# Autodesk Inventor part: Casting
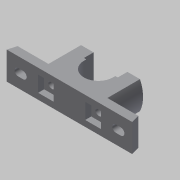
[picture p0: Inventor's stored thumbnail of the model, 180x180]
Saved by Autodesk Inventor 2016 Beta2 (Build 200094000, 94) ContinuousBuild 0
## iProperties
Created: 2009-04
Part Number: Casting
Document SubType Name: Modeling
Designer: Sham
Density: 1 g/cm^3
Material: Generic
Appearance: Default
Author: Sham
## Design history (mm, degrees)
sketch "Sketch1"
  geometry: L1 (-104, 0)-(104, 0); L2 (-104, 0)-(-100, 14); L3 (-100, 14)-(100, 14); L4 (100, 14)-(104, 0); 1 further point
  constraints: 8 end point, 1 horizontal, 1 midpoint, 1 parallel, 1 other
  dimensions: "d0" = 208 distance of L1.start L1.end; "d1" = 104 distance of L1.end point (0, 0); "d2" = 4 horizontal distance of L1.start L2.end; "d3" = 4 horizontal distance of L1.end L3.end; "d10" = 14 distance between parallel lines of L1 L3
extrude "Extrusion1" new body sketch "Sketch1" stored distance "d4" = 46; taper "d5" = 0 deg
sketch "Sketch2"
  geometry: L1 (51.143, 46)-(148.857, 46); L2 (148.857, 0)-(51.143, 0); A1 r 54 centre (100, 23) between (51.143, 46) and (51.143, 0); A2 r 54 centre (100, 23) between (148.857, 0) and (148.857, 46)
  constraints: 4 end point, 4 point on circle, 2 centre point, 1 parallel
extrude "Extrusion2" join sketch "Sketch2" distance "d8" = 54; taper "d9" = 0 deg
sketch "Sketch3"
  geometry: L1 (-28, 68)-(-28, 52); L2 (-28, 52)-(-24, 52); L3 (28, 68)-(28, 52); L4 (28, 52)-(24, 52); L5 (-28, 68)-(28, 68); L6 (-100, 14)-(-48.857, 14) reference; L7 (0, 48)-(0, 19); L8 (48.857, 14)-(100, 14) reference; L9 (48.857, 68)-(-48.857, 68) reference; L10 (-24, 48)-(-24, 52); L11 (24, 48)-(24, 52); A1 r 24 centre (0, 48) between (-24, 48) and (24, 48); 1 further point
  constraints: 16 end point, 5 perpendicular, 2 point on circle, 2 symmetric about line, 1 centre point, 1 tangent, 1 vertical alignment, 1 other
  dimensions: "d11" = 16 distance of L1.start L1.end; "d16" = 24 radius of A1; "d17" = 16 distance of L3.start L3.end; "d52" = 56 distance between parallel lines of L1 L3; "d54" = 54 distance between parallel lines of L8 L9 (derived)
extrude "Extrusion3" cut sketch "Sketch3" distance "d18" = 54; taper "d19" = 0 deg
sketch "Sketch4"
  geometry: L1 (-23, 29)-(-15, 29); L2 (-15, 17)-(-23, 17); L3 (-185, 29)-(-177, 29); L4 (-177, 17)-(-185, 17); A1 r 6 centre (-15, 23) between (-15, 17) and (-15, 29); A2 r 6 centre (-23, 23) between (-23, 29) and (-23, 17); A3 r 6 centre (-177, 23) between (-177, 17) and (-177, 29); A4 r 6 centre (-185, 23) between (-185, 29) and (-185, 17)
  constraints: 8 end point, 8 point on circle, 8 tangent, 4 centre point, 3 parallel
  dimensions: "d20" = 8 distance of A1.centre A2.centre; "d21" = 6 radius of A1; "d24" = 6 radius of A3; "d25" = 8 distance of A4.centre A3.centre
extrude "Extrusion4" cut sketch "Sketch4" distance "d28" = 54; taper "d29" = 0 deg
sketch "Sketch5"
  geometry: L1 (208, 0)-(0, 0) reference; L2 (52, -10)-(78, -10); L3 (78, -10)-(78, -36); L4 (78, -36)-(52, -36); L5 (52, -36)-(52, -10); L6 (130, -10)-(156, -10); L7 (156, -10)-(156, -36); L8 (156, -36)-(130, -36); L9 (130, -36)-(130, -10); L10 (0, -46)-(208, -46) reference; L11 (104, -23)-(104, -46)
  constraints: 18 end point, 5 perpendicular, 4 parallel, 2 horizontal, 1 midpoint
  dimensions: "d30" = 26 distance of L2.start L2.end; "d31" = 10 distance between parallel lines of L2 L1; "d32" = 10 distance between parallel lines of L1 L6; "d65" = 26 distance between parallel lines of L3 L11; "d66" = 26 distance between parallel lines of L9 L11
extrude "Extrusion5" cut sketch "Sketch5" distance "d34" = 10; taper "d35" = 0 deg
sketch "Sketch6"
  geometry: L1 (148.857, 0)-(128, 0) reference; L2 (72, 0)-(51.143, 0) reference; L3 (0, 46)-(0, 0) reference; L4 (200, 46)-(200, 0) reference; C1 r 6 at (61, 23); C2 r 6 at (139, 23); 1 further point
  constraints: 2 centre point, 1 equal radius
  dimensions: "d36" = 12 diameter of C1; "d37" = 78 distance of C2.centre C1.centre; "d39" = 39 distance of C2.centre point (100, 23); "d58" = 39 distance of C1.centre point (100, 23); "d59" = 23 distance from line of L1 C2.centre; "d60" = 23 distance from line of L2 C1.centre; "d61" = 61 distance from line of L3 C1.centre; "d62" = 61 distance from line of L4 C2.centre (derived)
extrude "Extrusion6" cut sketch "Sketch6" stored distance "d40" = 10; taper "d41" = 0 deg
workplane "Work Plane1"
sketch "Sketch7"
  geometry: L1 (-4, 46)-(204, 46) reference; L2 (-4, 0)-(-4, 46) reference; 1 further point
  dimensions: "d43" = 23 distance from line of L1 point (100, 23); "d44" = 104 distance from line of point (100, 23) L2
hole "Hole1" sketch "Sketch7" at (100, 23) diameter "d45" = 8; stored, may be unused: countersink angle "d49" = 90 deg, drill point angle "d51" = 118 deg; dims "d46" = 6, "d47" = 8, "d48" = 16, "d50" = 8
body "Solid1"
other parameters: "d6" = 108, "d42" = -52
